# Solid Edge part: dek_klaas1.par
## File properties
Author: Mac
Template: Normal.par
Last saved by: Mac
Revision: 14
Application: Solid Edge
Density: 2595,000 kg/m^3
Accuracy: 0,990
Material: Glass, general industrial
Face Style: White (glass)
Fill Style: ANSI36(Marble)
Virtual Style: White (Glass)
Coef. of Thermal Exp: 0.0
Thermal Conductivity: 0.0
Specific Heat: 0.0
Modulus of Elasticity: 0.0
Poission's Ratio: 0.0
Yield Stress: 0.0
Ultimate Stress: 0.0
Elongation: 0.0
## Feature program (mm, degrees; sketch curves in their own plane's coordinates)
sketch for "unnamed Protrusion 1" plane through (0, 0, 0) normal (0, 0, 1) x-axis (1, 0, 0)
extrude "unnamed Protrusion 1" add to key point along +normal
replace surface "unnamed ReplaceSurface 1"
sketch for "unnamed Cutout 1" plane through (17.2231, 15.1706, 0) normal (0, 0, -1) x-axis (1, 0, 0)
  line (59.2433, 13.6622) -> (-66.6267, 13.6622)
  line (-66.6267, 50.0572) -> (-66.6267, 13.6622)
  line (-66.6267, 50.0572) -> (59.2433, 50.0572)
  line (59.2433, 50.0572) -> (59.2433, 13.6622)
extrude "unnamed Cutout 1" cut through along -normal
replace surface "unnamed ReplaceSurface 2"
sketch used by "ExtrudedCutout_9" plane through (0, -47.6819, 0) normal (0, -1, 0) x-axis (1, 0, 0)
  line (-35.7364, 3.4307) -> (-34.3085, 16.0628)
  bspline degree 3 poles (-6.2668, 3.4315) (-12.7024, 8.2679) (-22.0496, 12.4784) (-34.3085, 16.0628) knots 0 1 multiplicities 4 4
  line (-6.2658, 3.4307) -> (-35.7364, 3.4307)
extrude "ExtrudedCutout_9" cut finite 90.8743 along -normal
thinwall "Thinwall_4"  Thickness = 0.08 mm
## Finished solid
Body 1: sheet body, 1 face, 6 edges, 6 vertices.
  Faces by surface: spline 1
  Edges by curve: spline 6
Body 2: solid body, 6 faces, 12 edges, 8 vertices.
  Faces by surface: plane 3, offset 1, spline 1, swept 1
  Edges by curve: intersection 7, line 4, curve on surface 1
Body 3: sheet body, 1 face, 4 edges, 4 vertices.
  Faces by surface: spline 1
  Edges by curve: spline 4
Bounding box of the edges (mm; curved faces can reach further): 97.793 x 30.322 x 34.114, from (-32.1251, 0, 0) to (65.6678, 30.3223, 34.1136).
Planar faces by outward normal: -x 1, -z 1, oblique 1
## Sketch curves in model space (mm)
spline (-6.2668, -47.6819, 3.4315) -> (-18.1039, -47.6819, 10.2166) -> (-34.3085, -47.6819, 16.0628)
line (-6.2658, -47.6819, 3.4307) -> (-35.7364, -47.6819, 3.4307)
line (-35.7364, -47.6819, 3.4307) -> (-34.3085, -47.6819, 16.0628)
spline (-7.395, 25.9435, 34.1136) -> (-19.2834, 27.357, 34.1136) -> (-32.1251, 28.4997, 34.1136)
spline (0.7256, 0, 34.1136) -> (-1.5887, 13.3712, 34.1136) -> (-7.395, 25.9435, 34.1136)
spline (65.6678, 0, 0) -> (40.22, 0, 17.3758) -> (0.7256, 0, 34.1136)
line (-32.1251, 0, 0) -> (65.6678, 0, 0)
spline (65.6678, 0, 0) -> (63.3536, 13.3712, 0) -> (57.5472, 25.9435, 0)
spline (57.5472, 25.9435, 0) -> (34.8062, 28.3456, 0) -> (8.6507, 29.8164, 0)
spline (8.6507, 29.8164, 0) -> (-10.9903, 30.2656, 0) -> (-32.1251, 30.2669, 0)
line (-32.1251, 30.2669, 0) -> (-32.1251, 0, 0)
spline (57.5472, 25.9435, 0) -> (32.0994, 25.9435, 17.3758) -> (-7.395, 25.9435, 34.1136)
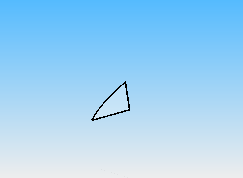
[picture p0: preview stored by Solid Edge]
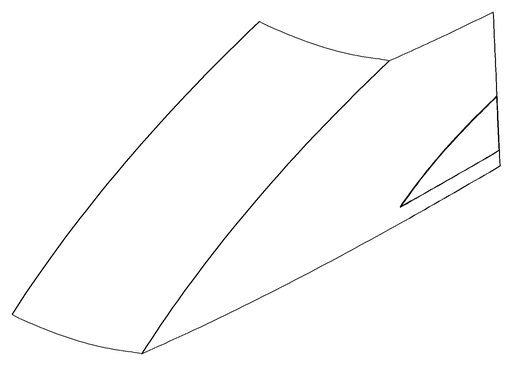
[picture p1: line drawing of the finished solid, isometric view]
